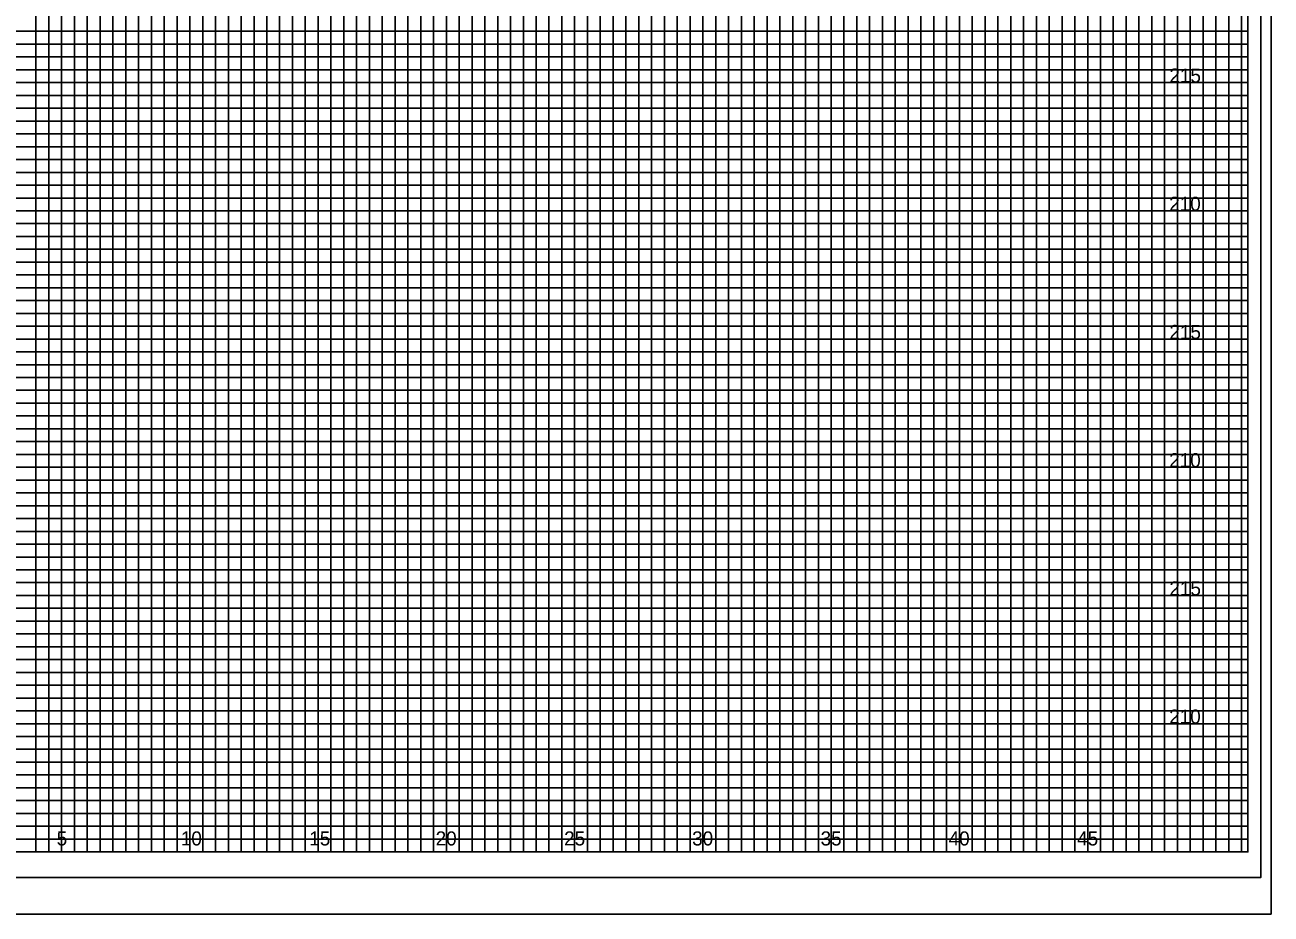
# Model space of a CAD drawing. Extents: x -4 to 103, y -2 to 67.
# Drawn here: x 54.82 to 103.4, y -2.43 to 32.25 of the extents above; entities that cross this region are included whole.
import ezdxf

# ---------------------------------------------------------------- set-up
doc = ezdxf.new("R2010")
doc.units = 0
for name, color, linetype in [('Old_Level_10', 7, 'Continuous'), ('Old_Level_16', 7, 'Continuous'), ('Old_Level_3', 7, 'Continuous'), ('Old_Level_5', 7, 'Continuous'), ('Old_Level_8', 7, 'Continuous'), ('Prop XS Dump Level', 7, 'Continuous'), ('Prop XS EOT Tick Mark', 7, 'Continuous'), ('Prop XS Subgrade Concrete', 7, 'Continuous'), ('Typical Curb CELL', 7, 'Continuous')]:
    doc.layers.add(name, color=color, linetype=linetype)

msp = doc.modelspace()

# ---------------------------------------------------------------- linework, layer by layer
at = {"layer": 'Old_Level_10'}
for p, q in [((56.25, 0), (56.25, 65)), ((58.75, 0), (58.75, 65)), ((61.25, 0), (61.25, 65)), ((63.75, 0), (63.75, 65)), ((66.25, 0), (66.25, 65)), ((68.75, 0), (68.75, 65)), ((71.25, 0), (71.25, 65)), ((73.75, 0), (73.75, 65)), ((91.25, 0), (91.25, 63.425)), ((93.75, 0), (93.75, 63.425)), ((96.25, 0), (96.25, 63.425)), ((98.75, 0), (98.75, 63.425)), ((101.25, 0), (101.25, 63.425)), ((76.25, 0), (76.25, 62)), ((78.75, 0), (78.75, 62)), ((81.25, 0), (81.25, 62)), ((83.75, 0), (83.75, 62)), ((86.25, 0), (86.25, 62)), ((88.75, 0), (88.75, 62)), ((0, 30), (102.5, 30)), ((0, 27.5), (102.5, 27.5)), ((0, 25), (102.5, 25)), ((0, 22.5), (102.5, 22.5)), ((0, 20), (102.5, 20)), ((0, 17.5), (102.5, 17.5)), ((0, 15), (102.5, 15)), ((0, 12.5), (102.5, 12.5)), ((0, 10), (102.5, 10)), ((0, 7.5), (102.5, 7.5)), ((0, 5), (102.5, 5)), ((0, 2.5), (102.5, 2.5))]:
    msp.add_line(p, q, dxfattribs=at)
at = {"layer": 'Old_Level_3'}
msp.add_line((-3.5, -2.425), (103.4, -2.425), dxfattribs=at)
at = {"layer": 'Old_Level_5'}
msp.add_lwpolyline([(103.4, 67.4), (-3.5, 67.4), (-3.5, -2.425), (103.4, -2.425)], close=True, dxfattribs=at)
at = {"layer": 'Old_Level_8'}
for points in [[(56.25, 0), (56.25, 65)], [(58.75, 65), (58.75, 0), (61.25, 0), (61.25, 65)], [(63.75, 65), (63.75, 0), (66.25, 0), (66.25, 65)], [(68.75, 65), (68.75, 0), (71.25, 0), (71.25, 65)], [(73.75, 65), (73.75, 0), (76.25, 0), (76.25, 62)], [(88.75, 62), (88.75, 0), (91.25, 0), (91.25, 63.425)], [(93.75, 63.425), (93.75, 0), (96.25, 0), (96.25, 63.425)], [(98.75, 63.425), (98.75, 0), (101.25, 0), (101.25, 63.425)], [(78.75, 62), (78.75, 0), (81.25, 0), (81.25, 62)], [(83.75, 62), (83.75, 0), (86.25, 0), (86.25, 62)], [(0, 27.5), (102.5, 27.5), (102.5, 30), (0, 30)], [(0, 22.5), (102.5, 22.5), (102.5, 25), (0, 25)], [(0, 17.5), (102.5, 17.5), (102.5, 20), (0, 20)], [(0, 12.5), (102.5, 12.5), (102.5, 15), (0, 15)], [(0, 7.5), (102.5, 7.5), (102.5, 10), (0, 10)], [(0, 2.5), (102.5, 2.5), (102.5, 5), (0, 5)]]:
    msp.add_lwpolyline(points, dxfattribs=at)
at = {"layer": 'Prop XS Dump Level'}
for points in [[(54.75, 0), (55.25, 0), (55.25, 65)], [(55.75, 65), (55.75, 0), (56.75, 0), (56.75, 65)], [(57.25, 65), (57.25, 0), (57.75, 0), (57.75, 65)], [(58.25, 65), (58.25, 0), (59.25, 0), (59.25, 65)], [(59.75, 65), (59.75, 0), (60.25, 0), (60.25, 65)], [(60.75, 65), (60.75, 0), (61.75, 0), (61.75, 65)], [(62.25, 65), (62.25, 0), (62.75, 0), (62.75, 65)], [(63.25, 65), (63.25, 0), (64.25, 0), (64.25, 65)], [(64.75, 65), (64.75, 0), (65.25, 0), (65.25, 65)], [(65.75, 65), (65.75, 0), (66.75, 0), (66.75, 65)], [(67.25, 65), (67.25, 0), (67.75, 0), (67.75, 65)], [(68.25, 65), (68.25, 0), (69.25, 0), (69.25, 65)], [(69.75, 65), (69.75, 0), (70.25, 0), (70.25, 65)], [(70.75, 65), (70.75, 0), (71.75, 0), (71.75, 65)], [(72.25, 65), (72.25, 0), (72.75, 0), (72.75, 65)], [(73.25, 65), (73.25, 0), (74.25, 0), (74.25, 62)], [(89.75, 62), (89.75, 0), (90.25, 0), (90.25, 63.425)], [(90.75, 63.425), (90.75, 0), (91.75, 0), (91.75, 63.425)], [(92.25, 63.425), (92.25, 0), (92.75, 0), (92.75, 63.425)], [(93.25, 63.425), (93.25, 0), (94.25, 0), (94.25, 63.425)], [(94.75, 63.425), (94.75, 0), (95.25, 0), (95.25, 63.425)], [(95.75, 63.425), (95.75, 0), (96.75, 0), (96.75, 63.425)], [(97.25, 63.425), (97.25, 0), (97.75, 0), (97.75, 63.425)], [(98.25, 63.425), (98.25, 0), (99.25, 0), (99.25, 63.425)], [(99.75, 63.425), (99.75, 0), (100.25, 0), (100.25, 63.425)], [(100.25, 63.425), (100.75, 63.425), (100.75, 0), (101.75, 0), (101.75, 63.425), (102.25, 63.425), (102.25, 0)], [(74.75, 62), (74.75, 0), (75.25, 0), (75.25, 62)], [(75.75, 62), (75.75, 0), (76.75, 0), (76.75, 62)], [(77.25, 62), (77.25, 0), (77.75, 0), (77.75, 62)], [(78.25, 62), (78.25, 0), (79.25, 0), (79.25, 62)], [(79.75, 62), (79.75, 0), (80.25, 0), (80.25, 62)], [(80.75, 62), (80.75, 0), (81.75, 0), (81.75, 62)], [(82.25, 62), (82.25, 0), (82.75, 0), (82.75, 62)], [(83.25, 62), (83.25, 0), (84.25, 0), (84.25, 62)], [(84.75, 62), (84.75, 0), (85.25, 0), (85.25, 62)], [(85.75, 62), (85.75, 0), (86.75, 0), (86.75, 62)], [(87.25, 62), (87.25, 0), (87.75, 0), (87.75, 62)], [(88.25, 62), (88.25, 0), (89.25, 0), (89.25, 62)], [(0, 31.5), (102.5, 31.5), (102.5, 32), (0, 32)], [(0, 30.5), (102.5, 30.5), (102.5, 31), (0, 31)], [(0, 29), (102.5, 29), (102.5, 29.5), (0, 29.5)], [(0, 28), (102.5, 28), (102.5, 28.5), (0, 28.5)], [(0, 26.5), (102.5, 26.5), (102.5, 27), (0, 27)], [(0, 25.5), (102.5, 25.5), (102.5, 26), (0, 26)], [(0, 24), (102.5, 24), (102.5, 24.5), (0, 24.5)], [(0, 23), (102.5, 23), (102.5, 23.5), (0, 23.5)], [(0, 21.5), (102.5, 21.5), (102.5, 22), (0, 22)], [(0, 20.5), (102.5, 20.5), (102.5, 21), (0, 21)], [(0, 19), (102.5, 19), (102.5, 19.5), (0, 19.5)], [(0, 18), (102.5, 18), (102.5, 18.5), (0, 18.5)], [(0, 16.5), (102.5, 16.5), (102.5, 17), (0, 17)], [(0, 15.5), (102.5, 15.5), (102.5, 16), (0, 16)], [(0, 14), (102.5, 14), (102.5, 14.5), (0, 14.5)], [(0, 13), (102.5, 13), (102.5, 13.5), (0, 13.5)], [(0, 11.5), (102.5, 11.5), (102.5, 12), (0, 12)], [(0, 10.5), (102.5, 10.5), (102.5, 11), (0, 11)], [(0, 9), (102.5, 9), (102.5, 9.5), (0, 9.5)], [(0, 8), (102.5, 8), (102.5, 8.5), (0, 8.5)], [(0, 6.5), (102.5, 6.5), (102.5, 7), (0, 7)], [(0, 5.5), (102.5, 5.5), (102.5, 6), (0, 6)], [(0, 4), (102.5, 4), (102.5, 4.5), (0, 4.5)], [(0, 3), (102.5, 3), (102.5, 3.5), (0, 3.5)], [(0, 1.5), (102.5, 1.5), (102.5, 2), (0, 2)], [(0, 0.5), (102.5, 0.5), (102.5, 1), (0, 1)]]:
    msp.add_lwpolyline(points, dxfattribs=at)
at = {"layer": 'Prop XS Subgrade Concrete'}
msp.add_lwpolyline([(102.5, 65), (0, 65), (0, 0), (102.5, 0)], close=True, dxfattribs=at)
at = {"layer": 'Typical Curb CELL'}
msp.add_lwpolyline([(103, 66), (-2.8, 66), (-2.8, -1), (103, -1)], close=True, dxfattribs=at)

# ---------------------------------------------------------------- texts
at = {"layer": 'Old_Level_16'}
for s, p in [('5', (56.0574, 0.25)), ('10', (60.8971, 0.25)), ('15', (65.9057, 0.25)), ('20', (70.8312, 0.25)), ('25', (75.8399, 0.25)), ('30', (80.8312, 0.25)), ('35', (85.8399, 0.25)), ('40', (90.8313, 0.25)), ('45', (95.8399, 0.25))]:
    msp.add_text(s, height=0.55, dxfattribs=at).set_placement(p)
at = {"layer": 'Prop XS EOT Tick Mark'}
for s, p in [('215', (99.4383, 30)), ('210', (99.4296, 25)), ('215', (99.4383, 20)), ('210', (99.4296, 15)), ('215', (99.4383, 10)), ('210', (99.4296, 5))]:
    msp.add_text(s, height=0.55, dxfattribs=at).set_placement(p)

doc.saveas('drawing.dxf')
